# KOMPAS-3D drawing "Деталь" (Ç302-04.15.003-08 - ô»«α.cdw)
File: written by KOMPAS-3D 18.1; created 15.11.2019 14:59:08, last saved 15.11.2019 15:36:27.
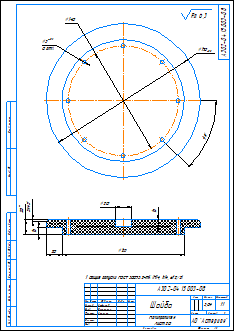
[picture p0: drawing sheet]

Sheet 1: A3, portrait

Document properties: Параметр неуказанной шероховатости: Ra 6,3; Масса: 3.83777

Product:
- Part/product: Деталь
    Масса: 3.83777
    source file: А302-04.15.003-08 - Упор.cdw

Title block, sheet 1: Наименование: Шайба; designation: А302-04.15.003-08; Материал: Полипропилен / Лист 20; Масса: 3,84; Количество листов документа: 1; organisation: АО "Астерион"; Форматы листов документа: A3; stored path: D:\Мембранные насосы\Мембранный электропривод\А302-00.00.000 - ASTRA-302 (МЭ200)\А302-04.00.000 - Мембранный насос ASTRA-302-PP\А302-04.15.003-08 - Упор.cdw; Разработал: Лифлянд; Проверил: Борисенко; Т. контр.: Лучихин

Views: Вид 1, Спереди, Проекционный вид 2, Местный разрез 1
Referenced files in C:\Users\User\Desktop\: Упор из листа 20.m3d
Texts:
  Ra 6,3
Dimensions and other numbers on the sheet: 196; 5; 8 отв.; 140; 20; 10; 155; 3; 1; 1:1; 3,84

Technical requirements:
  Общие допуски ГОСТ 30893.2-mK (H14, h14,  t2/2).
